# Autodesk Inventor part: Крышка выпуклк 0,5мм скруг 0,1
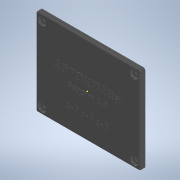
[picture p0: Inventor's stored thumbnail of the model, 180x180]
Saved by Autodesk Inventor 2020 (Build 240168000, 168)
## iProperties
Created: 2023-11
Part Number: Крышка выпуклк 0,5мм скруг 0,1
Material: Типовые
Document SubType Name: Modeling
Designer: User
Density: 1 g/cm^3
Appearance: Темно-серый
Author: User
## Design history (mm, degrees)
sketch "Эскиз1"
  geometry: L1 (-59.717, 50)-(60.283, 50); L2 (60.283, 50)-(60.283, -50); L3 (60.283, -50)-(-59.717, -50); L4 (-59.717, -50)-(-59.717, 50); C1 r 2 at (-52.717, 43); C2 r 2 at (-52.717, -43); C3 r 2 at (53.283, 43); C4 r 2 at (53.283, -43); 2 further points
  constraints: 8 end point, 4 centre point, 2 parallel, 1 horizontal, 1 perpendicular
extrude "Выдавливание1" new body sketch "Эскиз1" distance "d14" = 6; taper "d15" = 0 deg
sketch "Эскиз2"
  geometry: C1 r 2 at (-52.717, 43) reference; C2 r 4.25 at (-52.717, 43); C3 r 2 at (53.283, 43) reference; C4 r 4.25 at (53.283, 43); C5 r 2 at (-52.717, -43) reference; C6 r 4.25 at (-52.717, -43); C7 r 2 at (53.283, -43) reference; C8 r 4.25 at (53.283, -43); 1 further point
  constraints: 4 centre point, 4 coincident
  dimensions: "d16" = 8.5 diameter of C2; "d17" = 8.5 diameter of C4; "d18" = 8.5 diameter of C6; "d19" = 8.5 diameter of C8
extrude "Выдавливание2" cut sketch "Эскиз2" distance "d20" = 3; taper "d21" = 0 deg
fillet "Сопряжение1" dims "d22" = 2
fillet "Сопряжение2" dims "d23" = 1
sketch "Эскиз3"
  geometry: L1 (-24.129, 14.205)-(21.804, 14.205); L2 (21.804, 14.205)-(21.804, -23.839); L3 (21.804, -23.839)-(-24.129, -23.839); L4 (-24.129, -23.839)-(-24.129, 14.205); 1 further point
  constraints: 2 other
feature "Рельеф1" sketch "Эскиз3" dims "d24" = 0.75, "d25" = 0
fillet "Сопряжение3" dims "d26" = 0.1
fillet "Сопряжение4" dims "d27" = 0.1
fillet "Сопряжение5" dims "d28" = 0.1
fillet "Сопряжение6" dims "d29" = 0.1
fillet "Сопряжение7" dims "d30" = 0.1
fillet "Сопряжение8" dims "d31" = 0.1
fillet "Сопряжение9" dims "d32" = 0.1
fillet "Сопряжение10" dims "d33" = 0.1
sketch "Эскиз4"
  geometry: 1 further point
node "Твердое тело1"
